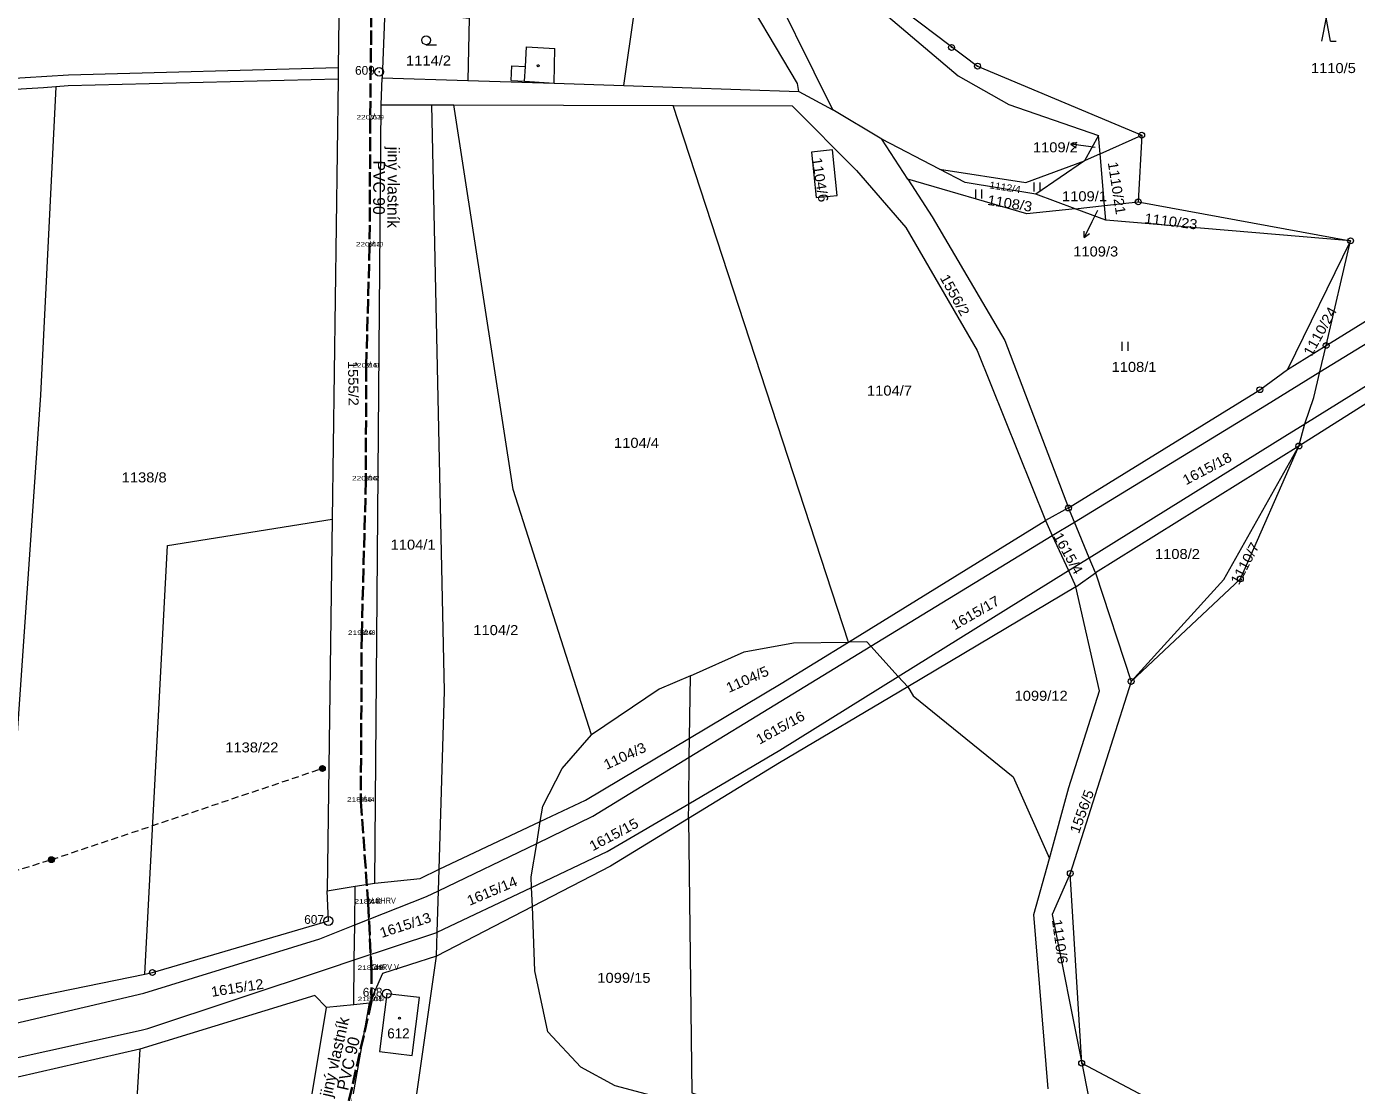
# Model space of a CAD drawing. Extents: x -686207 to -681951, y -1020493 to -1017811.
# Drawn here: x -684321.3 to -684095.1, y -1019504.1 to -1019323.9 of the extents above; entities that cross this region are included whole.
import ezdxf
from ezdxf.enums import TextEntityAlignment as Align

# ---------------------------------------------------------------- set-up
doc = ezdxf.new("R2010")
doc.units = 0
doc.header["$LTSCALE"] = 0.4
doc.header["$PDMODE"] = 32
doc.header["$PDSIZE"] = 0.2
doc.linetypes.add('LONG_DASHED', pattern=[7.5, 6, -1.5])
doc.linetypes.add('MEDIUM_DASHED', pattern=[4.5, 3, -1.5])
for name, color, linetype, lineweight in [('1', 7, 'Continuous', 13), ('25', 7, 'Continuous', 13), ('3', 7, 'Continuous', 13), ('35', 7, 'LONG_DASHED', 35), ('4', 7, 'Continuous', 13), ('5', 7, 'Continuous', 13), ('6', 7, 'Continuous', 13), ('7', 7, 'Continuous', 13), ('8', 7, 'Continuous', 13)]:
    doc.layers.add(name, color=color, linetype=linetype, lineweight=lineweight)
doc.layers.add('17', color=7, linetype='Continuous')
doc.layers.add('2', color=7, linetype='Continuous')

msp = doc.modelspace()

# ---------------------------------------------------------------- linework, layer by layer
at = {"layer": '1'}
for p, q in [((-684268.33, -1019332.89), (-684269.33, -1019407.76)), ((-684261.02, -1019337.23), (-684260.84, -1019332.67)), ((-684260.84, -1019332.67), (-684246.28, -1019333.11)), ((-684219.74, -1019333.97), (-684189.99, -1019335.01)), ((-684189.99, -1019335.01), (-684184.19, -1019338.1)), ((-684262.06, -1019469.67), (-684261.02, -1019337.23)), ((-684261.02, -1019337.23), (-684252.38, -1019337.25)), ((-684252.38, -1019337.25), (-684248.67, -1019337.26)), ((-684248.67, -1019337.26), (-684211.32, -1019337.35)), ((-684181.5, -1019428.66), (-684211.32, -1019337.35)), ((-684138.73, -1019345.6), (-684131.64, -1019342.43)), ((-684131.64, -1019342.43), (-684132.23, -1019353.77)), ((-684166.05, -1019348.19), (-684175.86, -1019343.07)), ((-684141.36, -1019346.78), (-684149.64, -1019352.47)), ((-684142.98, -1019354.93), (-684149.64, -1019352.47)), ((-684137.98, -1019354.39), (-684132.23, -1019353.77)), ((-684132.23, -1019353.77), (-684096.11, -1019360.4)), ((-684142.98, -1019354.93), (-684137.98, -1019354.39)), ((-684137.77, -1019356.86), (-684142.98, -1019354.93)), ((-684137.77, -1019356.86), (-684137.98, -1019354.39)), ((-684096.11, -1019360.4), (-684137.77, -1019356.86)), ((-684096.11, -1019360.4), (-684106.82, -1019382.27)), ((-684100.27, -1019378.22), (-684096.11, -1019360.4)), ((-684072.05, -1019374.52), (-684104.9, -1019395.31)), ((-684106.82, -1019382.27), (-684100.27, -1019378.22)), ((-684104.9, -1019395.31), (-684139.51, -1019416.88)), ((-684144.1, -1019405.85), (-684148.03, -1019408)), ((-684269.33, -1019407.76), (-684270.18, -1019471.01)), ((-684181.5, -1019428.66), (-684148.03, -1019408)), ((-684142.83, -1019419.25), (-684139.51, -1019416.88)), ((-684139.51, -1019416.88), (-684133.44, -1019435.36)), ((-684142.83, -1019419.25), (-684171.44, -1019436.26)), ((-684133.44, -1019435.36), (-684143.79, -1019468.03)), ((-684141.85, -1019500.32), (-684143.79, -1019468.03)), ((-684235.29, -1019473.69), (-684251.59, -1019482.14)), ((-684260.17, -1019542.07), (-684251.59, -1019482.14)), ((-684265.67, -1019490.39), (-684270.3, -1019490.87)), ((-684263, -1019490.12), (-684265.67, -1019490.39)), ((-684302.05, -1019497.96), (-684326.6, -1019503.54)), ((-684302.05, -1019497.96), (-684303.71, -1019525.08)), ((-684141.85, -1019500.32), (-684140.7, -1019506.07))]:
    msp.add_line(p, q, dxfattribs=at)
for points in [[(-684209.35, -1019202.26), (-684185.49, -1019306.24), (-684179.53, -1019318.14), (-684162.86, -1019332.32), (-684154.27, -1019337.22), (-684139, -1019342.47)], [(-684189.99, -1019335.01), (-684190.21, -1019333.6), (-684201.22, -1019314.94), (-684205.19, -1019307.76), (-684207.56, -1019301.2), (-684212.19, -1019287.54)], [(-684184.19, -1019338.1), (-684196.84, -1019312.52), (-684200.81, -1019305.34), (-684207.19, -1019287.34)], [(-684267.9, -1019301.39), (-684268.3, -1019330.88), (-684268.33, -1019332.89)], [(-684183.21, -1019301.53), (-684176.53, -1019317.8), (-684159.56, -1019330.66), (-684131.64, -1019342.43)], [(-684260.11, -1019315.34), (-684260.38, -1019321.02), (-684260.84, -1019332.67)], [(-684260.38, -1019321.02), (-684246.02, -1019322.53), (-684246.28, -1019333.11)], [(-684246.28, -1019333.11), (-684231.6, -1019333.56), (-684219.74, -1019333.97), (-684217.9, -1019321.33)], [(-684381.27, -1019346.56), (-684376.08, -1019345.32), (-684371.61, -1019343.88), (-684356.52, -1019337.72), (-684340.04, -1019333.72), (-684314.17, -1019332.17), (-684268.3, -1019330.88)], [(-684268.33, -1019332.89), (-684314.24, -1019334.02), (-684316.37, -1019334.22)], [(-684316.37, -1019334.22), (-684318.43, -1019334.36), (-684331.87, -1019335.14), (-684339.89, -1019335.57)], [(-684316.37, -1019334.22), (-684318.95, -1019386.68), (-684323.56, -1019453.16), (-684326.18, -1019490.28), (-684301.22, -1019485.17)], [(-684251.14, -1019467.33), (-684250.23, -1019437.03), (-684252.38, -1019337.25)], [(-684225.25, -1019444.43), (-684238.57, -1019402.68), (-684248.67, -1019337.26)], [(-684211.32, -1019337.35), (-684191.1, -1019337.4), (-684180.18, -1019348.43), (-684171.75, -1019358.11), (-684159.64, -1019379.08), (-684148.03, -1019408)], [(-684171.41, -1019349.92), (-684175.86, -1019343.07), (-684184.19, -1019338.1)], [(-684138.73, -1019345.6), (-684139, -1019342.47), (-684141.36, -1019346.78)], [(-684166.05, -1019348.19), (-684151.34, -1019350.48), (-684141.36, -1019346.78)], [(-684137.98, -1019354.39), (-684138.73, -1019345.6), (-684141.36, -1019346.78)], [(-684149.64, -1019352.47), (-684161.66, -1019350.48), (-684166.05, -1019348.19)], [(-684171.41, -1019349.92), (-684167.27, -1019356.3), (-684154.94, -1019377.35), (-684144.1, -1019405.85)], [(-684142.98, -1019354.93), (-684151.19, -1019355.82), (-684171.41, -1019349.92)], [(-684100.27, -1019378.22), (-684082.74, -1019367.38), (-684071.5, -1019361.03)], [(-684104.9, -1019395.31), (-684103.9, -1019391.52), (-684102.34, -1019387.08), (-684101.32, -1019382.71), (-684100.27, -1019378.22)], [(-684144.1, -1019405.85), (-684111.54, -1019385.73), (-684106.82, -1019382.27)], [(-684133.44, -1019435.36), (-684117.65, -1019418), (-684104.9, -1019395.31)], [(-684133.44, -1019435.36), (-684114.86, -1019417.93), (-684104.9, -1019395.31)], [(-684139.51, -1019416.88), (-684140.58, -1019414.32), (-684143.1, -1019408.26), (-684144.1, -1019405.85)], [(-684301.22, -1019485.17), (-684297.34, -1019412.23), (-684269.33, -1019407.76)], [(-684148.03, -1019408), (-684146.85, -1019410.55), (-684144.1, -1019416.51), (-684142.83, -1019419.25)], [(-684147.35, -1019465.48), (-684144.02, -1019453.41), (-684138.81, -1019436.97), (-684142.83, -1019419.25)], [(-684208.54, -1019445.01), (-684192.97, -1019435.74), (-684181.5, -1019428.66)], [(-684208.39, -1019434.41), (-684199.25, -1019430.31), (-684190.89, -1019428.82), (-684181.5, -1019428.66)], [(-684171.44, -1019436.26), (-684173.04, -1019434.5), (-684177.69, -1019429.38), (-684178.39, -1019428.61), (-684181.5, -1019428.66)], [(-684208.39, -1019434.41), (-684213.73, -1019436.66), (-684225.25, -1019444.43)], [(-684208.74, -1019458.7), (-684208.7, -1019456.17), (-684208.59, -1019448.27), (-684208.54, -1019445.01), (-684208.39, -1019434.41)], [(-684171.44, -1019436.26), (-684193.24, -1019449.23), (-684208.74, -1019458.7)], [(-684171.44, -1019436.26), (-684170.53, -1019437.84), (-684153.48, -1019451.59), (-684147.35, -1019465.48)], [(-684233.95, -1019459.2), (-684233.53, -1019456.6), (-684230.24, -1019450.18), (-684225.25, -1019444.43)], [(-684233.95, -1019459.2), (-684226.26, -1019455.56), (-684208.54, -1019445.01)], [(-684251.59, -1019482.14), (-684251.46, -1019478.01), (-684251.25, -1019470.98), (-684251.14, -1019467.33), (-684233.95, -1019459.2)], [(-684235.29, -1019473.69), (-684235.41, -1019470.42), (-684235.48, -1019468.64), (-684234.55, -1019462.92), (-684233.95, -1019459.2)], [(-684208.74, -1019458.7), (-684222.01, -1019466.81), (-684235.29, -1019473.69)], [(-684208.74, -1019458.7), (-684208.16, -1019505.38), (-684177.69, -1019515.75)], [(-684147.58, -1019504.67), (-684150, -1019475.05), (-684147.35, -1019465.48)], [(-684262.06, -1019469.67), (-684254.39, -1019468.87), (-684251.14, -1019467.33)], [(-684143.79, -1019468.03), (-684146.9, -1019475.05), (-684141.85, -1019500.32)], [(-684301.22, -1019485.17), (-684299.92, -1019484.9), (-684269.99, -1019476.12), (-684270.18, -1019471.01)], [(-684270.18, -1019471.01), (-684265.43, -1019470.23), (-684262.06, -1019469.67)], [(-684265.67, -1019490.39), (-684265.58, -1019482.74), (-684265.51, -1019476.81), (-684265.43, -1019470.23)], [(-684177.69, -1019515.75), (-684221.21, -1019504.16), (-684227.02, -1019501), (-684232.68, -1019495.01), (-684234.88, -1019484.62), (-684235.29, -1019473.69)], [(-684251.59, -1019482.14), (-684260.77, -1019485.09), (-684263, -1019490.12)], [(-684270.3, -1019490.87), (-684272.31, -1019488.83), (-684302.05, -1019497.96)], [(-684278.02, -1019537.85), (-684277.4, -1019533.48), (-684270.3, -1019490.87)], [(-684276.02, -1019576.63), (-684272.81, -1019545.6), (-684263, -1019490.12)], [(-684141.85, -1019500.32), (-684128.34, -1019507.47), (-684080.22, -1019521.13), (-684028.07, -1019536.98)]]:
    msp.add_lwpolyline(points, dxfattribs=at)
for points in [[(-684183.42, -1019352.66), (-684184.21, -1019344.94), (-684187.81, -1019345.31), (-684187.02, -1019353.03)], [(-684254.5, -1019489.17), (-684260.03, -1019488.5), (-684261.29, -1019498.33), (-684255.74, -1019499.03)]]:
    msp.add_lwpolyline(points, close=True, dxfattribs=at)
for p in [(-684262.86, -1019339.73), (-684262.97, -1019361.35), (-684263.56, -1019381.94), (-684263.61, -1019401.16), (-684264.31, -1019427.44), (-684264.47, -1019455.81), (-684263.2, -1019473.16), (-684262.67, -1019484.44), (-684262.65, -1019489.77)]:
    msp.add_point(p, dxfattribs=at)
at = {"layer": '25'}
msp.add_line((-684262.67, -1019484.44), (-684263.2, -1019473.16), dxfattribs=at)
at = {"layer": '3'}
for p, q in [((-684099.54, -1019326.42), (-684098.544, -1019326.42)), ((-684253.363, -1019327.02), (-684251.613, -1019327.02)), ((-684149.911, -1019351.99), (-684149.911, -1019350.49)), ((-684148.91, -1019351.99), (-684148.91, -1019350.49)), ((-684159.841, -1019353.18), (-684159.841, -1019351.68)), ((-684158.84, -1019353.18), (-684158.84, -1019351.68)), ((-684134.951, -1019379.11), (-684134.951, -1019377.61)), ((-684133.95, -1019379.11), (-684133.95, -1019377.61))]:
    msp.add_line(p, q, dxfattribs=at)
msp.add_lwpolyline([(-684099.54, -1019326.42), (-684100.29, -1019322.42), (-684101.04, -1019326.42)], dxfattribs=at)
msp.add_circle((-684253.3629, -1019326.2698), 0.75, dxfattribs=at)
at = {"layer": '35'}
msp.add_lwpolyline([(-684261.329, -1019307.032), (-684261.35, -1019310.13), (-684262.62, -1019315.63), (-684262.86, -1019339.73), (-684262.97, -1019361.35), (-684263.56, -1019381.94), (-684263.61, -1019401.16), (-684264.31, -1019427.44), (-684264.47, -1019455.81), (-684263.2, -1019473.16), (-684262.67, -1019484.44), (-684262.65, -1019489.77), (-684267.48, -1019511.11), (-684271.99, -1019538.81), (-684274.98, -1019561.61), (-684276.868, -1019579.309)], dxfattribs=at)
at = {"layer": '4'}
for p, q in [((-684236.27, -1019327.37), (-684231.47, -1019327.68)), ((-684231.6, -1019333.56), (-684231.47, -1019327.68)), ((-684238.92, -1019333.11), (-684238.77, -1019330.62)), ((-684238.77, -1019330.62), (-684236.48, -1019330.76)), ((-684238.92, -1019333.11), (-684236.63, -1019333.25)), ((-684236.63, -1019333.25), (-684231.6, -1019333.56)), ((-684101.32, -1019382.71), (-684079.72, -1019369.4)), ((-684103.9, -1019391.52), (-684074.23, -1019373.07)), ((-684110.41, -1019388.31), (-684101.32, -1019382.71)), ((-684143.1, -1019408.26), (-684110.41, -1019388.31)), ((-684107.31, -1019393.64), (-684103.9, -1019391.52)), ((-684140.58, -1019414.32), (-684107.31, -1019393.64)), ((-684146.85, -1019410.55), (-684143.1, -1019408.26)), ((-684177.69, -1019429.38), (-684146.85, -1019410.55)), ((-684144.1, -1019416.51), (-684140.58, -1019414.32)), ((-684173.04, -1019434.5), (-684144.1, -1019416.51)), ((-684193.03, -1019438.74), (-684177.69, -1019429.38)), ((-684193.2, -1019447.04), (-684173.04, -1019434.5)), ((-684208.59, -1019448.27), (-684193.03, -1019438.74)), ((-684224.99, -1019458.31), (-684208.59, -1019448.27)), ((-684208.7, -1019456.17), (-684193.2, -1019447.04)), ((-684222.55, -1019464.33), (-684208.7, -1019456.17)), ((-684234.55, -1019462.92), (-684224.99, -1019458.31)), ((-684251.25, -1019470.98), (-684234.55, -1019462.92)), ((-684235.41, -1019470.42), (-684222.55, -1019464.33)), ((-684253.3, -1019471.97), (-684251.25, -1019470.98)), ((-684251.46, -1019478.01), (-684235.41, -1019470.42)), ((-684265.51, -1019476.81), (-684253.3, -1019471.97)), ((-684270.04, -1019478.61), (-684265.51, -1019476.81)), ((-684265.58, -1019482.74), (-684251.72, -1019478.13)), ((-684251.72, -1019478.13), (-684251.46, -1019478.01)), ((-684301.39, -1019488.42), (-684271.42, -1019479.16)), ((-684271.42, -1019479.16), (-684270.04, -1019478.61)), ((-684270.16, -1019484.27), (-684265.58, -1019482.74)), ((-684300.7, -1019494.44), (-684270.16, -1019484.27)), ((-684326.31, -1019494.23), (-684301.39, -1019488.42))]:
    msp.add_line(p, q, dxfattribs=at)
for points in [[(-684236.63, -1019333.25), (-684236.48, -1019330.76), (-684236.27, -1019327.37)], [(-684325.66, -1019499.97), (-684301.82, -1019494.69), (-684300.7, -1019494.44)]]:
    msp.add_lwpolyline(points, dxfattribs=at)
at = {"layer": '5'}
for centre in [(-684234.2868, -1019330.5992), (-684257.8968, -1019492.6492)]:
    msp.add_circle(centre, 0.175, dxfattribs=at)
at = {"layer": '6', "linetype": 'MEDIUM_DASHED'}
for p, q in [((-684317.09, -1019465.69), (-684271, -1019450.17)), ((-684365, -1019480.44), (-684317.09, -1019465.69))]:
    msp.add_line(p, q, dxfattribs=at)
at = {"layer": '6'}
for centre, radius in [((-684271.0034, -1019450.1699), 0.5), ((-684271.0034, -1019450.1699), 0.4), ((-684271.0034, -1019450.1699), 0.3), ((-684271.0034, -1019450.1699), 0.2), ((-684271.0034, -1019450.1699), 0.1), ((-684317.0934, -1019465.6899), 0.5), ((-684317.0934, -1019465.6899), 0.4), ((-684317.0934, -1019465.6899), 0.3), ((-684317.0934, -1019465.6899), 0.2), ((-684317.0934, -1019465.6899), 0.1)]:
    msp.add_circle(centre, radius, dxfattribs=at)
at = {"layer": '7'}
for p, q in [((-684143.692, -1019343.952), (-684142.77, -1019344.588)), ((-684139.17, -1019355.22), (-684140.12, -1019357.15)), ((-684141.436, -1019359.847), (-684140.546, -1019359.167))]:
    msp.add_line(p, q, dxfattribs=at)
for points in [[(-684139.55, -1019344.54), (-684140.72, -1019344.37), (-684143.692, -1019343.952), (-684142.63, -1019343.596)], [(-684140.12, -1019357.15), (-684141.436, -1019359.847), (-684141.447, -1019358.728)]]:
    msp.add_lwpolyline(points, dxfattribs=at)
at = {"layer": '8'}
for centre, radius in [((-684163.98, -1019327.4899), 0.5), ((-684163.98, -1019327.4899), 0.0303), ((-684261.34, -1019331.6398), 0.75), ((-684159.56, -1019330.6599), 0.5), ((-684159.56, -1019330.6599), 0.0303), ((-684261.34, -1019331.6398), 0.03), ((-684131.64, -1019342.4299), 0.5), ((-684131.64, -1019342.4299), 0.0303), ((-684132.23, -1019353.7699), 0.5), ((-684132.23, -1019353.7699), 0.0303), ((-684096.11, -1019360.3999), 0.5), ((-684096.11, -1019360.3999), 0.0303), ((-684100.27, -1019378.2199), 0.5), ((-684100.27, -1019378.2199), 0.0303), ((-684111.54, -1019385.7299), 0.5), ((-684111.54, -1019385.7299), 0.0303), ((-684104.9, -1019395.3099), 0.5), ((-684104.9, -1019395.3099), 0.0303), ((-684144.1, -1019405.8499), 0.5), ((-684144.1, -1019405.8499), 0.0303), ((-684114.86, -1019417.9299), 0.5), ((-684114.86, -1019417.9299), 0.0303), ((-684133.44, -1019435.3599), 0.5), ((-684133.44, -1019435.3599), 0.0303), ((-684143.79, -1019468.0299), 0.5), ((-684143.79, -1019468.0299), 0.0303), ((-684269.99, -1019476.1198), 0.75), ((-684269.99, -1019476.1198), 0.03), ((-684299.92, -1019484.8999), 0.5), ((-684299.92, -1019484.8999), 0.0303), ((-684260.03, -1019488.4998), 0.75), ((-684260.03, -1019488.4998), 0.03), ((-684141.85, -1019500.3199), 0.5), ((-684141.85, -1019500.3199), 0.0303)]:
    msp.add_circle(centre, radius, dxfattribs=at)

# ---------------------------------------------------------------- texts
at = {"layer": '17'}
for s, rotation, p in [('jiný vlastník', 269.708, (-684259.9186, -1019351.2949)), ('PVC 90', 269.708, (-684262.3639, -1019351.3359)), ('jiný vlastník', 77.247, (-684267.9197, -1019499.4628)), ('PVC 90', 77.247, (-684265.6227, -1019500.6023))]:
    msp.add_text(s, height=2, rotation=rotation, dxfattribs=at).set_placement(p, align=Align.CENTER)
at = {"layer": '2', "width": 1.1}
for s, p in [('1114/2', (-684256.775, -1019330.57)), ('1110/5', (-684102.86, -1019331.85)), ('1109/2', (-684150.15, -1019345.33)), ('1109/1', (-684145.2, -1019353.66)), ('1109/3', (-684143.29, -1019363.059)), ('1108/1', (-684136.77, -1019382.7)), ('1104/7', (-684178.37, -1019386.73)), ('1104/4', (-684221.4, -1019395.62)), ('1138/8', (-684305.14, -1019401.5)), ('1104/1', (-684259.4, -1019412.94)), ('1108/2', (-684129.39, -1019414.53)), ('1104/2', (-684245.33, -1019427.48)), ('1099/12', (-684153.27, -1019438.66)), ('1138/22', (-684287.52, -1019447.44)), ('1099/15', (-684224.23, -1019486.65))]:
    msp.add_text(s, height=1.7, dxfattribs=at).set_placement(p)
at = {"layer": '2'}
for s, height, p in [('0139', 0.75, (-684262.86, -1019339.73)), ('0140', 0.75, (-684262.97, -1019361.35)), ('0141', 0.75, (-684263.56, -1019381.94)), ('0142', 0.75, (-684263.61, -1019401.16)), ('0143', 0.75, (-684264.31, -1019427.44)), ('0144', 0.75, (-684264.47, -1019455.81)), ('0145', 0.75, (-684263.2, -1019473.16)), ('0146', 0.75, (-684262.67, -1019484.44)), ('0147', 0.75, (-684262.65, -1019489.77)), ('612', 1.7, (-684259.964, -1019496.1))]:
    msp.add_text(s, height=height, dxfattribs=at).set_placement(p)
at = {"layer": '2', "width": 1.1}
for s, height, rotation, p in [('1104/6', 1.7, 279, (-684187.769, -1019346.362)), ('1110/21', 1.7, 279, (-684137.419, -1019347.082)), ('1112/4', 1.19, 351, (-684157.613, -1019351.447)), ('1108/3', 1.7, 351, (-684157.982, -1019354.259)), ('1110/23', 1.7, 353, (-684131.253, -1019357.373)), ('1556/2', 1.7, 299, (-684166.026, -1019366.69)), ('1110/24', 1.7, 61, (-684102.746, -1019380.162)), ('1555/2', 1.7, 271, (-684266.667, -1019380.839)), ('1615/18', 1.7, 28, (-684124.12, -1019402.01)), ('1615/4', 1.7, 299, (-684146.753, -1019410.642)), ('1110/7', 1.7, 62, (-684115.129, -1019419.059)), ('1615/17', 1.7, 30, (-684163.445, -1019426.686)), ('1104/5', 1.7, 24, (-684201.874, -1019437.336)), ('1615/16', 1.7, 29, (-684196.657, -1019446.153)), ('1104/3', 1.7, 25, (-684222.67, -1019450.43)), ('1556/5', 1.7, 70, (-684142.331, -1019461.38)), ('1615/15', 1.7, 28, (-684225.03, -1019464.29)), ('1615/14', 1.7, 23, (-684245.977, -1019473.562)), ('1615/13', 1.7, 18, (-684260.927, -1019479.028)), ('1110/6', 1.7, 278, (-684146.921, -1019475.968)), ('1615/12', 1.7, 9, (-684289.807, -1019489.039))]:
    msp.add_text(s, height=height, rotation=rotation, dxfattribs=at).set_placement(p)
at = {"layer": '3', "width": 1.4}
for s, p in [('220 63 ', (-684262.86, -1019339.73)), ('220 43 ', (-684262.97, -1019361.35)), ('220 16 ', (-684263.56, -1019381.94)), ('220 06 ', (-684263.61, -1019401.16)), ('219 29 ', (-684264.31, -1019427.44)), ('218 65 ', (-684264.47, -1019455.81)), ('218 48 ', (-684263.2, -1019473.16)), ('218 45 ', (-684262.67, -1019484.44)), ('218 05 ', (-684262.65, -1019489.77))]:
    msp.add_text(s, height=0.75, dxfattribs=at).set_placement(p, align=Align.CENTER)
at = {"layer": '4'}
for s, width, p in [('V', 0.85, (-684262.86, -1019339.73)), ('V', 0.85, (-684262.97, -1019361.35)), ('V', 0.85, (-684263.56, -1019381.94)), ('V', 0.85, (-684263.61, -1019401.16)), ('V', 0.85, (-684264.31, -1019427.44)), ('V', 0.85, (-684264.47, -1019455.81)), ('V CHRV', 0.9, (-684263.2, -1019473.16)), ('CHRV V', 0.9, (-684262.67, -1019484.44)), ('V', 0.85, (-684262.65, -1019489.77))]:
    msp.add_text(s, height=1, dxfattribs=dict(at, width=width)).set_placement(p)
at = {"layer": '8'}
for s, p in [('609', (-684265.443, -1019332.14)), ('607', (-684274.093, -1019476.62)), ('608', (-684264.133, -1019489))]:
    msp.add_text(s, height=1.5, dxfattribs=at).set_placement(p)

doc.saveas('drawing.dxf')
